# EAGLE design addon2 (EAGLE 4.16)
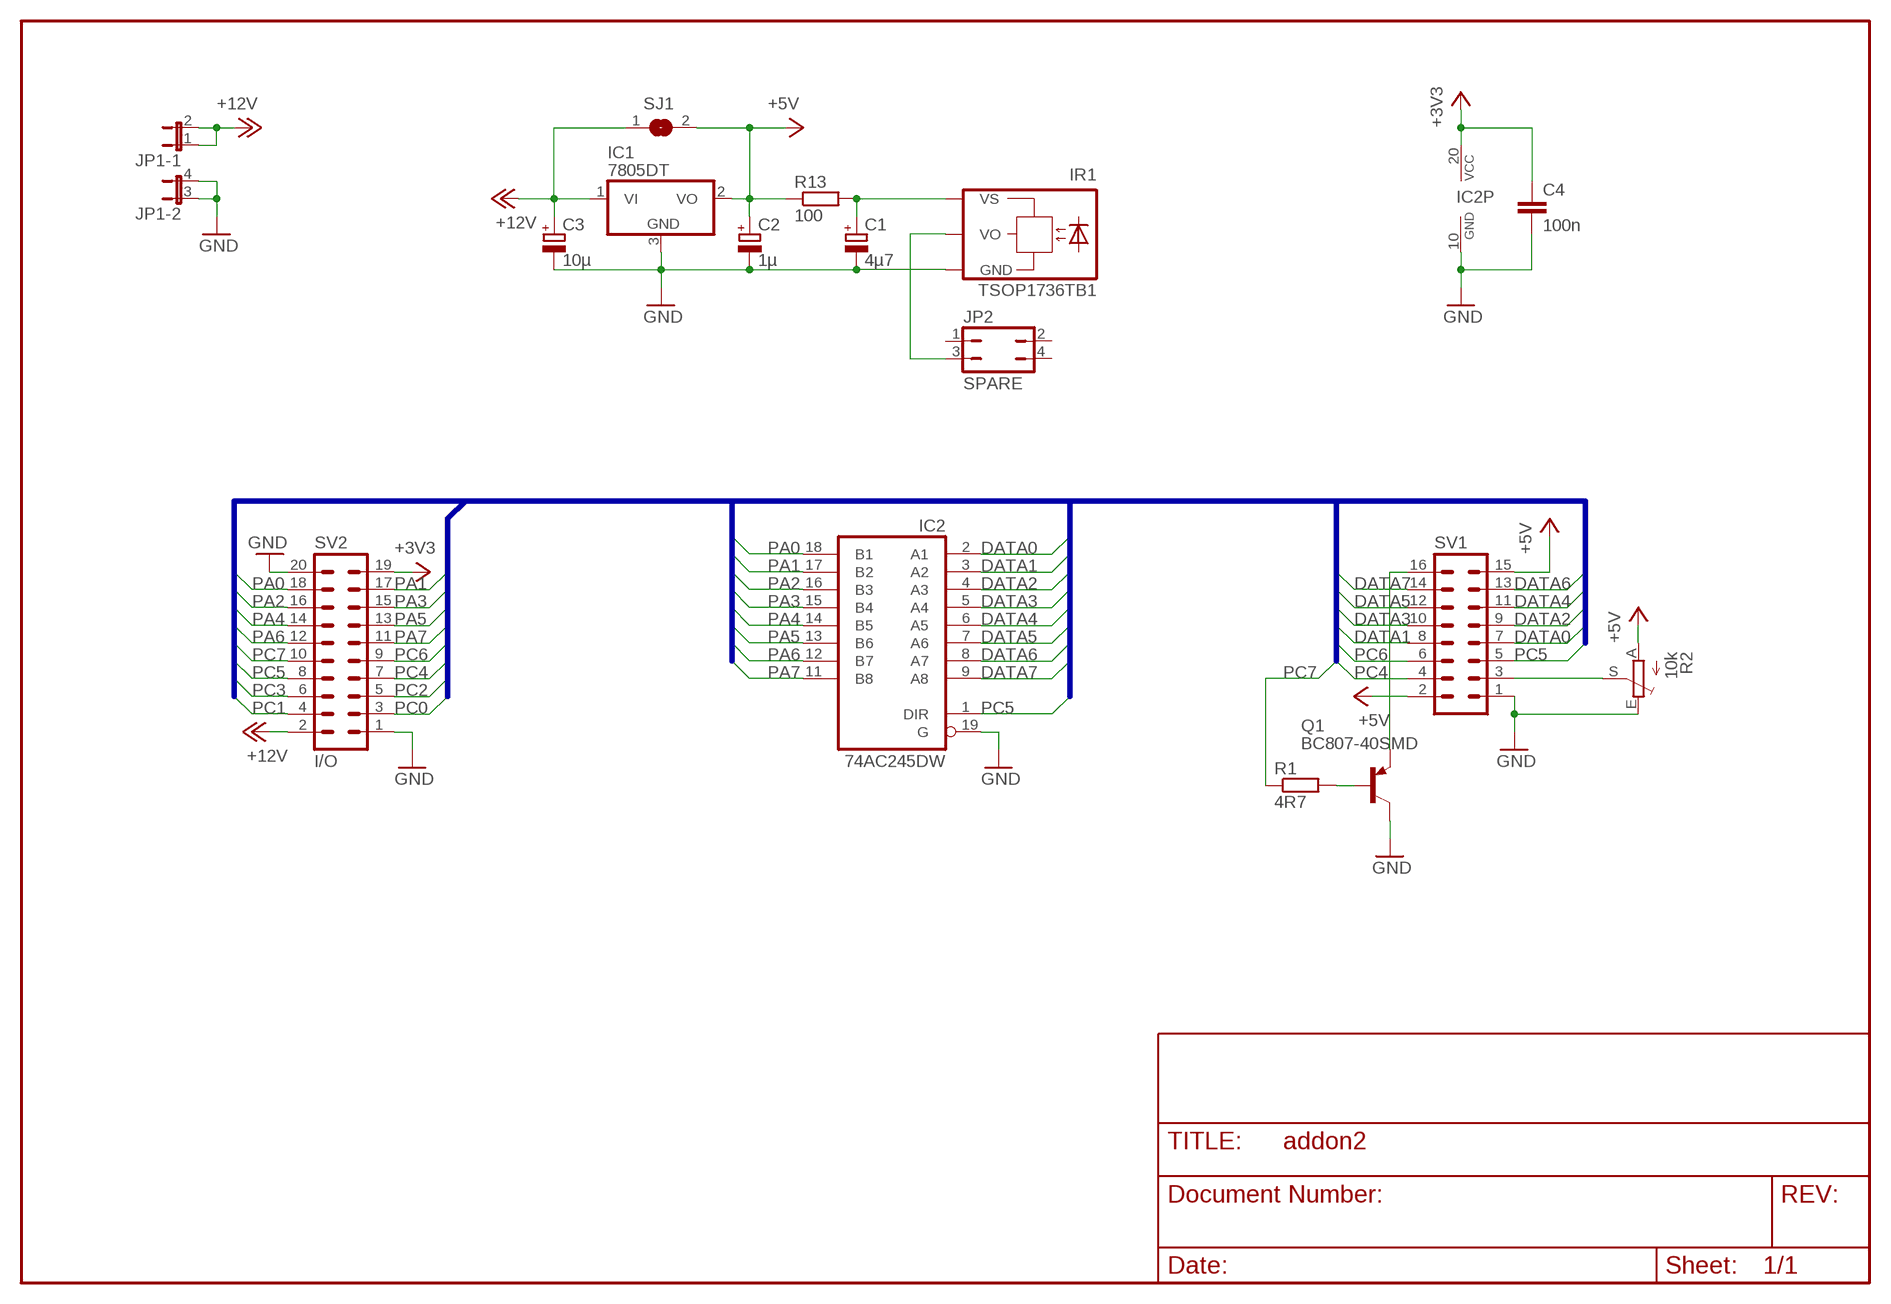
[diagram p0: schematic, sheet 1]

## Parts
C1  4µ7  CPOL-EUSMCA  [SMC_A]
C2  1µ  CPOL-EUSMCA  [SMC_A]
C3  10µ  CPOL-EUSMCD  [SMC_D]
C4  100n  C-EUC0805  [C0805]
IC1  7805DT  [TO252]
IC2  74AC245DW  [SO20W]
IR1  TSOP1736TB1  [TSOP17_TB1]
JP1  JP2QE  [JP2Q]
JP2  SPARE  JP2Q  [JP2Q]
Q1  BC807-40SMD  [SOT23-BEC]
R1  4R7  R-EU_R1206  [R1206]
R2  10k  TRIM_EU-LI10  [LI10]
R13  100  R-EU_R0805  [R0805]
SJ1  SJ  [SJ]
SV1  ML16L  [ML16L]
SV2  I/O  MA10-2  [MA10-2]

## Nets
+3V3: C4.1 IC2.20(VCC) SV2.19
+5V: C2.+ IC1.2(VO) R2.A R13.1 SJ1.2 SV1.2 SV1.15
+12V: C3.+ IC1.1(VI) JP1.1 JP1.2 SJ1.1 SV2.2
DATA0: IC2.2(A1) SV1.7
DATA1: IC2.3(A2) SV1.8
DATA2: IC2.4(A3) SV1.9
DATA3: IC2.5(A4) SV1.10
DATA4: IC2.6(A5) SV1.11
DATA5: IC2.7(A6) SV1.12
DATA6: IC2.8(A7) SV1.13
DATA7: IC2.9(A8) SV1.14
GND: C1.- C2.- C3.- C4.2 IC1.3(GND) IC2.10(GND) IC2.19(G) IR1.GND JP1.3 JP1.4 Q1.C R2.E SV1.1 SV2.1 SV2.20
N$1: R2.S SV1.3
N$2: Q1.B R1.2
N$3: Q1.E SV1.16
N$21: C1.+ IR1.VS R13.2
N$22: IR1.VO JP2.3
PA0: IC2.18(B1) SV2.18
PA1: IC2.17(B2) SV2.17
PA2: IC2.16(B3) SV2.16
PA3: IC2.15(B4) SV2.15
PA4: IC2.14(B5) SV2.14
PA5: IC2.13(B6) SV2.13
PA6: IC2.12(B7) SV2.12
PA7: IC2.11(B8) SV2.11
PC0: SV2.3
PC1: SV2.4
PC2: SV2.5
PC3: SV2.6
PC4: SV1.4 SV2.7
PC5: IC2.1(DIR) SV1.5 SV2.8
PC6: SV1.6 SV2.9
PC7: R1.1 SV2.10
Unconnected: JP2.1 JP2.2 JP2.4

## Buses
PA[0..7],PC[0..7],DATA[0..7]

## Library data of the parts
C1-C3 = rcl:CPOL-EU: POLARIZED CAPACITOR, European symbol
C4 = rcl:C-EU: CAPACITOR, European symbol
IC1 = linear:78*: Positive VOLTAGE REGULATOR Source: http://cache.national.com/ds/LM/LM78L05.pdf http://www.fairchildsemi.com/ds/LM/LM7805.pdf
IC2 = 74xx-eu:74*245: Octal BUS TRANSCEIVER, 3-state
IR1 = telefunken:TSOP17*TB1: TSOP17..TB1 IR Receiver Modules for Remote Control Systems Source: http://www.vishay.com/docs/82042/82042.pdf
JP1 = jumper:JP2QE: JUMPER
JP2 = jumper:JP2Q: JUMPER
Q1 = transistor-pnp:BC807*: PNP Transistror
R1 R13 = rcl:R-EU_: RESISTOR, European symbol
R2 = pot:TRIM_EU-: POTENTIOMETER
SJ1 = jumper:SJ: SMD solder JUMPER
SV1 = con-harting-ml:ML16: HARTING
SV2 = con-lstb:MA10-2: PIN HEADER

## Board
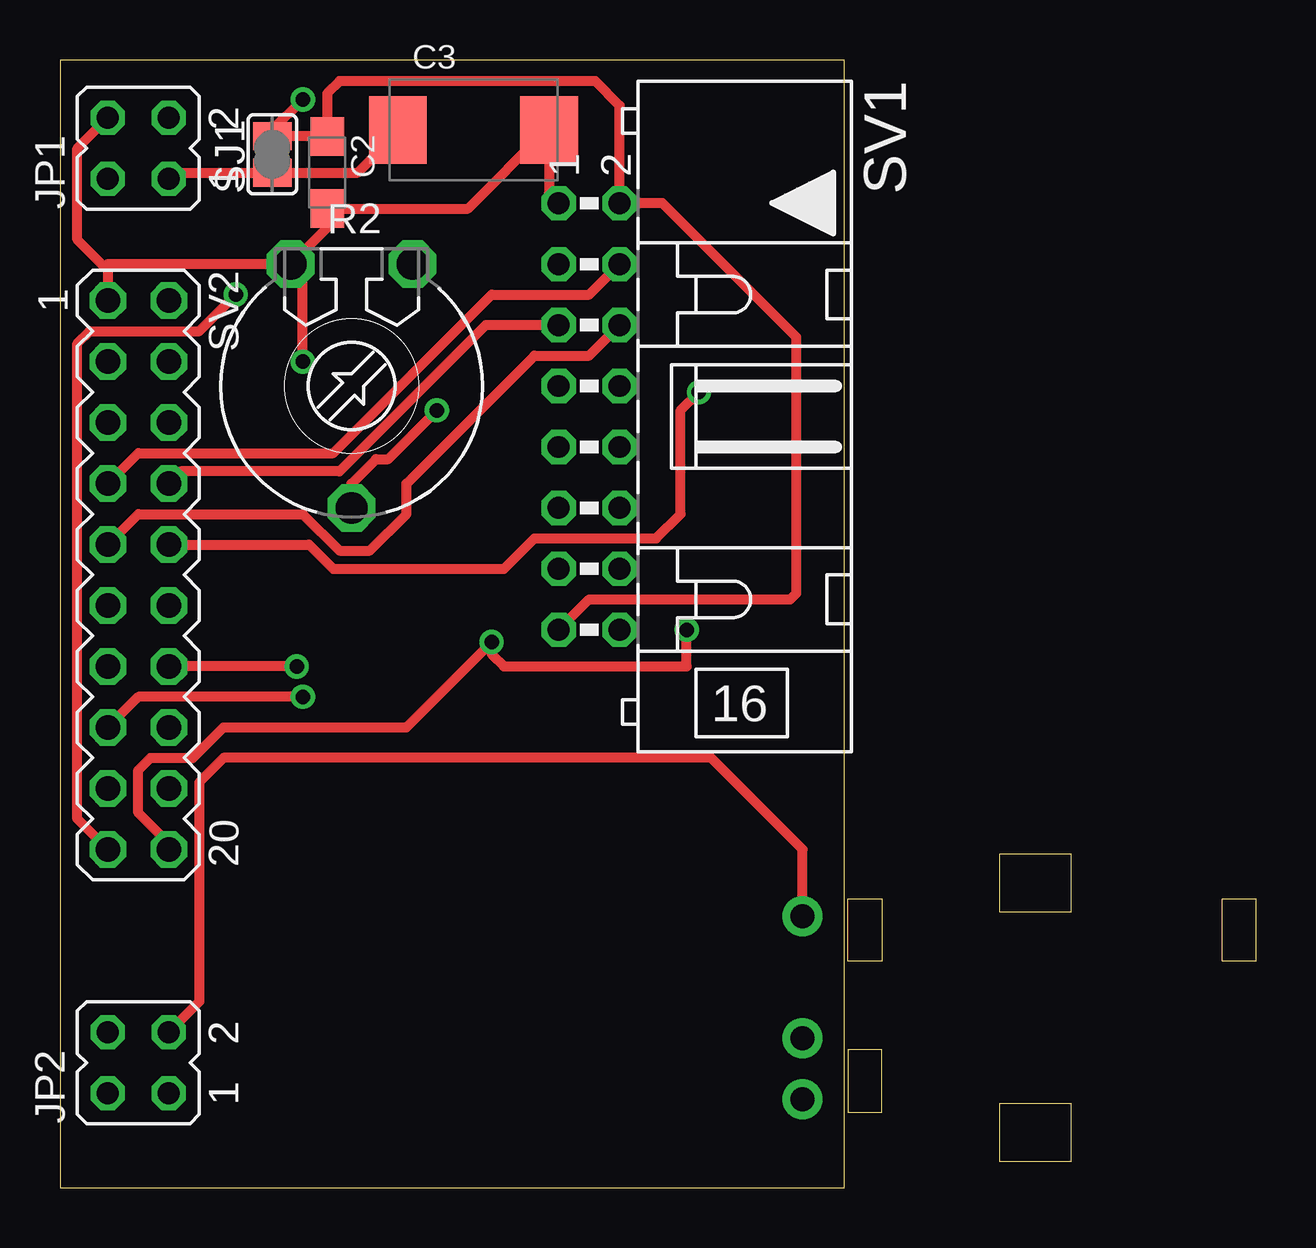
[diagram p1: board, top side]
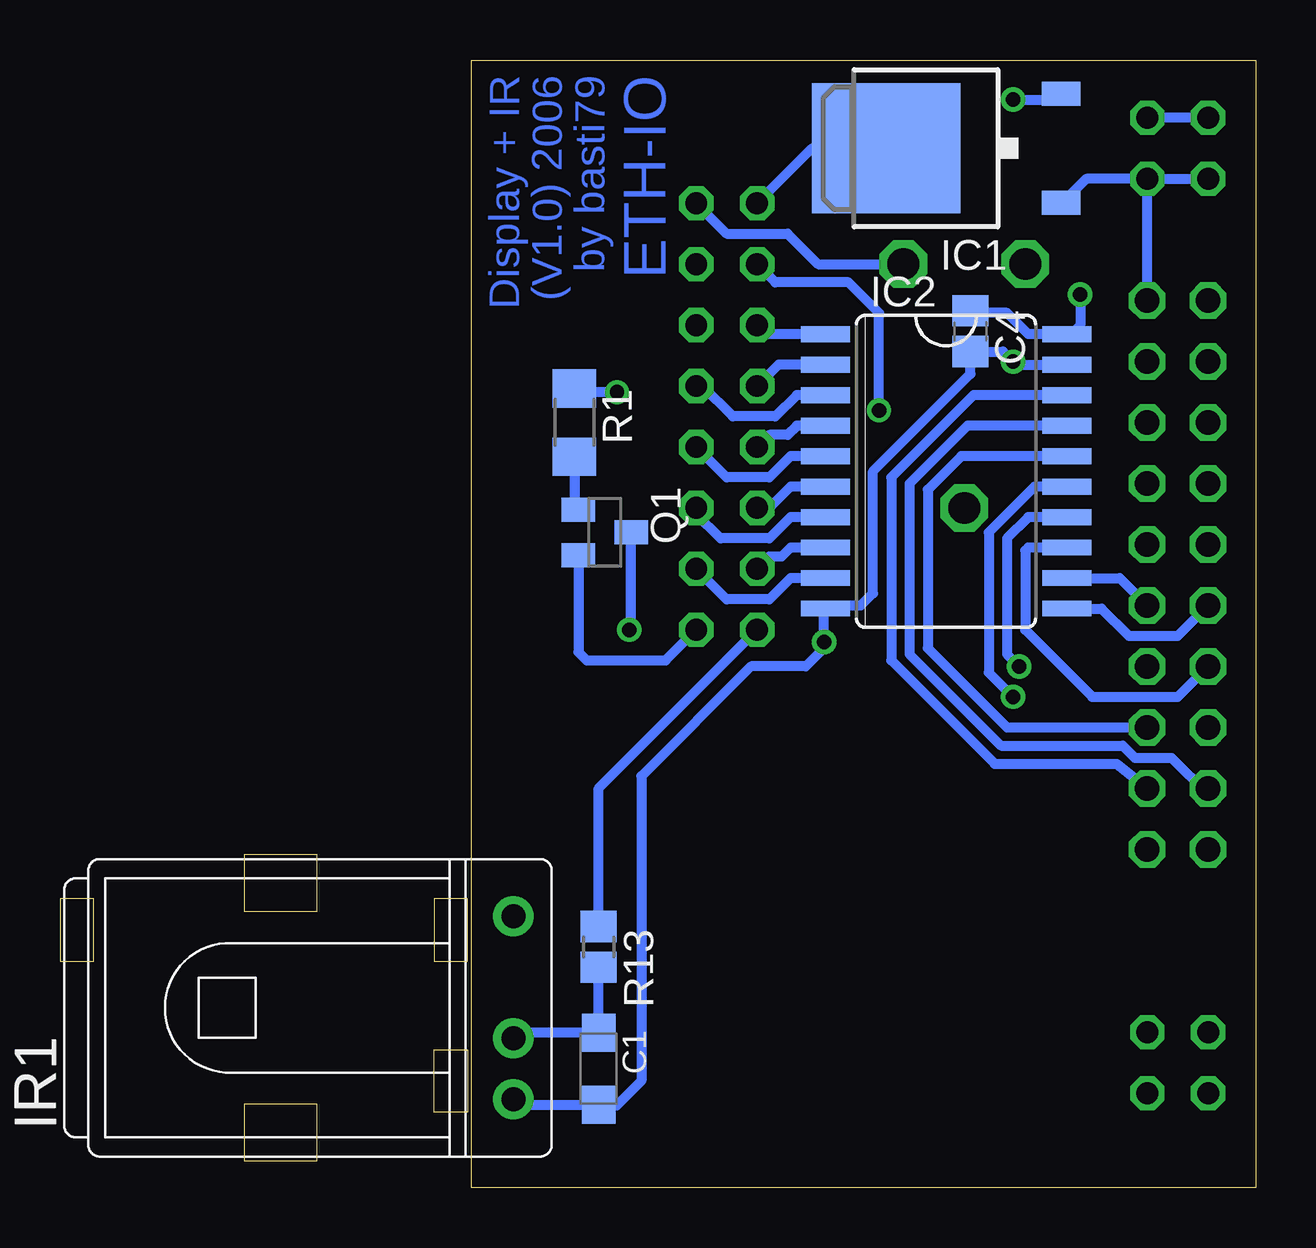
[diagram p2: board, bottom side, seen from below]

Size 49.85 x 46.98 mm. Coordinates in mm from the lower left corner, seen from the top.
Outline: 0,0 32.69,0 32.69,46.98 0,46.98 0,0
Copper layers (1*16): Top 0.035mm / dielectric 1.5mm / Bottom 0.035mm
Design rules "default": minimum track width 10mil, minimum drill 20mil, track to track 8mil, track to pad 8mil, pad to pad 8mil, via to via 8mil, smd to smd 8mil, copper to edge 20mil, drill to drill 8mil, minimum pad ring 10mil, minimum via ring 8mil, stop-mask expansion 4mil, vias tented up to drill 0mil, thermal gap 10mil
tKeepout: area 6.6,-0.1 to 23.3,16.9
bKeepout: area 6.6,-0.1 to 23.3,16.9; area 0,39.7 to 6.8,47.1; area 22.6,16.1 to 31.2,22.2

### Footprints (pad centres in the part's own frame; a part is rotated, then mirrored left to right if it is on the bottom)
SMC_A = smd 1.6 x 1.4: + -1.5,0; - 1.5,0
SMC_D = smd 2.4 x 2.8: + -3.15,0; - 3.15,0
C0805 = smd 1.3 x 1.5: 1 -0.85,0; 2 0.85,0
TO252 = smd 1 x 1.6: 1 -2.28,-4.8; 2 2.28,-4.8 | smd 5.4 x 6.2: 3 0,2.5
SO20W = smd 0.66 x 2.032: 1 -5.715,-5.029; 2 -4.445,-5.029; 3 -3.175,-5.029; 4 -1.905,-5.029; 5 -0.635,-5.029; 6 0.635,-5.029; 7 1.905,-5.029; 8 3.175,-5.029; 9 4.445,-5.029; 10 5.715,-5.029; 11 5.715,5.029; 12 4.445,5.029; 13 3.175,5.029; 14 1.905,5.029; 15 0.635,5.029; 16 -0.635,5.029; 17 -1.905,5.029; 18 -3.175,5.029; 19 -4.445,5.029; 20 -5.715,5.029
TSOP17_TB1 = drill 1 pad 1.676 round: GND 0,-3.81; VO 0,3.81; VS 0,-1.27
JP2Q = drill 0.914 octagon: 1 -1.27,-1.27; 2 -1.27,1.27; 3 1.27,-1.27; 4 1.27,1.27
SOT23-BEC = smd 1 x 1.4: B -0.95,-1.1; C 0,1.1; E 0.95,-1.1
R1206 = smd 1.6 x 1.803: 1 -1.422,0; 2 1.422,0
LI10 = drill 1.321 octagon: A -2.54,-5.08; E 2.54,-5.08; S 0,5.08
R0805 = smd 1.3 x 1.5: 1 -0.85,0; 2 0.85,0
SJ = smd 1.168 x 1.6: 1 -0.762,0; 2 0.762,0
ML16L = drill 0.914 octagon: 1 -8.89,-1.27; 2 -8.89,1.27; 3 -6.35,-1.27; 4 -6.35,1.27; 5 -3.81,-1.27; 6 -3.81,1.27; 7 -1.27,-1.27; 8 -1.27,1.27; 9 1.27,-1.27; 10 1.27,1.27; 11 3.81,-1.27; 12 3.81,1.27; 13 6.35,-1.27; 14 6.35,1.27; 15 8.89,-1.27; 16 8.89,1.27
MA10-2 = drill 1.016 octagon: 1 -11.43,-1.27; 2 -11.43,1.27; 3 -8.89,-1.27; 4 -8.89,1.27; 5 -6.35,-1.27; 6 -6.35,1.27; 7 -3.81,-1.27; 8 -3.81,1.27; 9 -1.27,-1.27; 10 -1.27,1.27; 11 1.27,-1.27; 12 1.27,1.27; 13 3.81,-1.27; 14 3.81,1.27; 15 6.35,-1.27; 16 6.35,1.27; 17 8.89,-1.27; 18 8.89,1.27; 19 11.43,-1.27; 20 11.43,1.27

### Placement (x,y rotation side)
C1  27.39,4.95 270 bottom
C2  11.14,42.29 270 top
C3  17.23,44.06 0 top
C4  11.9,35.68 270 bottom
IC1  12.92,43.3 90 bottom
IC2  12.92,29.84 270 bottom
IR1  30.95,7.49 0 bottom
JP1  3.26,43.3 90 top
JP2  3.26,5.2 90 top
Q1  27.14,27.3 270 bottom
R1  28.41,31.87 270 bottom
R2  12.15,33.4 180 top
R13  27.39,10.03 270 bottom
SJ1  8.85,43.05 90 top
SV1  22.06,32.13 270 top
SV2  3.26,25.52 270 top

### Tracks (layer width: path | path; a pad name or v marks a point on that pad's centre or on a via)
+3V3  (via drill 0.6)
  Top 0.406: SV2.19 0.72,15.36 0.72,35.17 1.23,35.68 5.8,35.68 v7.33,37.21
  Bottom 0.406: C4.1 11.9,36.44 10.38,36.44 9.49,35.55 IC2.20 7.89,35.48 7.84,35.43 7.33,35.94 v7.33,37.21
+5V  (via drill 0.6)
  Top 0.406: v10.12,45.33 8.85,44.06 SJ1.2 11.14,43.81 C2.+ 11.14,45.59 11.65,46.1 22.31,46.1 23.33,45.08 23.33,41.27 23.08,41.02 SV1.2 25.11,41.02 30.7,35.43 30.7,24.76 30.44,24.51 22.06,24.51 SV1.15
  Bottom 0.406: R2.A 18.25,38.48 19.52,39.75 22.06,39.75 SV1.2 | 8.1,45.58 8.09,45.59 | 8.1,45.58 IC1.2 | v10.12,45.33 8.34,45.33 8.1,45.58 | R13.1 27.39,16.63 SV1.15
+12V
  Top 0.406: C3.+ 14.19,44.06 12.41,42.29 SJ1.1 4.79,42.29 JP1.1
  Bottom 0.406: JP1.1 4.53,41.78 4.28,42.03 JP1.2 | 4.53,36.7 SV2.2 JP1.1 | IC1.1 8.1,41.02 8.09,41.02 7.07,42.03 JP1.1
DATA0
  Bottom 0.406: IC2.2 19.9,34.28 SV1.7
DATA1
  Bottom 0.406: IC2.3 19.14,33.02 20.03,32.13 21.81,32.13 23.08,33.4 SV1.8
DATA2
  Bottom 0.406: IC2.4 19.14,31.75 19.52,31.36 20.28,31.36 SV1.9
DATA3
  Bottom 0.406: IC2.5 19.39,30.48 20.28,29.59 22.06,29.59 SV1.10
DATA4
  Bottom 0.406: SV1.11 20.28,28.32 19.39,29.2 IC2.6
DATA5
  Bottom 0.406: IC2.7 19.39,27.93 20.28,27.05 22.31,27.05 23.33,28.06 SV1.12
DATA6
  Bottom 0.406: IC2.8 19.39,26.66 19.77,26.28 20.28,26.28 SV1.13
DATA7
  Bottom 0.406: IC2.9 19.39,25.39 20.28,24.51 22.06,24.51 SV1.14
GND  (via drill 0.6)
  Top 0.406: v10.12,34.41 10.12,37.97 R2.E | SV1.1 20.38,41.42 C3.- 20.28,44.06 17,40.79 C2.- 11.14,40 R2.E | v26.12,23.24 26.12,21.71 18.5,21.71 18,22.22 v18,22.73 14.44,19.17 6.82,19.17 5.55,17.9 3.77,17.9 3.26,17.39 3.26,15.62 4.53,14.35 SV2.20 | 1.99,38.22 1.99,38.48 R2.E | JP1.4 0.72,43.3 0.72,39.49 1.99,38.22 | 1.99,38.22 SV2.1
  Bottom 0.406: IC2.19 10,34.28 v10.12,34.41 10.54,34.83 C4.2 11.9,33.9 15.96,29.84 15.96,24.76 16.47,24.25 17.74,24.25 17.94,24.05 | 17.94,24.05 18,24 v18,22.73 18,22.47 18.76,21.71 21.04,21.71 25.62,17.14 25.62,4.44 26.63,3.42 30.44,3.42 30.7,3.68 IR1.GND 30.72,3.45 C1.- | 17.94,24.05 IC2.10 | JP1.4 JP1.3 | IC1.3 18.5,43.3 SV1.1 | Q1.C 26.04,23.32 v26.12,23.24
N$1  (via drill 0.6)
  Top 0.406: R2.S 12.15,29.33 13.17,30.35 13.68,30.35 v15.71,32.38
  Bottom 0.406: v15.71,32.38 15.71,36.44 16.98,37.71 20.03,37.71 SV1.3
N$2
  Bottom 0.406: Q1.B 28.34,28.25 28.41,28.32 R1.2
N$3
  Bottom 0.406: Q1.E 28.24,22.3 27.9,21.97 24.6,21.97 SV1.16
N$21
  Bottom 0.406: IR1.VS 30.7,6.22 30.47,6.45 C1.+ R13.2
N$22
  Top 0.406: IR1.VO 30.95,14.09 27.14,17.9 6.82,17.9 5.8,16.89 5.8,7.74 JP2.3
PA0
  Bottom 0.406: IC2.18 11.77,33.02 15.2,29.59 15.2,21.97 10.88,17.65 5.8,17.65 SV2.18
PA1
  Bottom 0.406: IC2.17 12.03,31.75 14.44,29.33 14.44,22.22 10.63,18.41 5.55,18.41 5.04,17.9 3.52,17.9 1.99,16.38 SV2.17
PA2
  Bottom 0.406: IC2.16 12.28,30.48 13.68,29.08 13.68,22.47 10.38,19.17 SV2.16
PA3  (via drill 0.6)
  Top 0.406: v10.12,20.44 3.26,20.44 SV2.15
  Bottom 0.406: IC2.15 9.23,29.2 11.14,27.3 11.14,21.46 v10.12,20.44
PA4  (via drill 0.6)
  Top 0.406: v9.87,21.71 SV2.14
  Bottom 0.406: IC2.14 9.49,27.93 10.38,27.05 10.38,22.22 v9.87,21.71
PA5
  Bottom 0.406: IC2.13 9.49,26.66 9.61,26.54 9.61,23.24 6.82,20.44 3.26,20.44 SV2.13
PA6
  Bottom 0.406: IC2.12 5.68,25.39 SV2.12
PA7
  Bottom 0.406: IC2.11 6.44,24.12 5.3,22.98 3.26,22.98 SV2.11
PC4
  Top 0.406: SV2.7 3.26,30.6 11.39,30.6 18,37.21 22.06,37.21 SV1.4
PC5
  Top 0.406: SV1.5 17.74,35.94 11.65,29.84 5.04,29.84 SV2.8
  Bottom 0.406: IC2.1 20.41,35.55 SV1.5
PC6
  Top 0.406: SV2.9 3.26,28.06 10.12,28.06 11.65,26.54 12.92,26.54 14.44,28.06 14.44,29.33 19.77,34.67 22.06,34.67 SV1.6
PC7  (via drill 0.6)
  Top 0.406: SV2.10 10.38,26.79 11.39,25.78 18.5,25.78 19.77,27.05 24.85,27.05 25.87,28.06 25.87,32.38 v26.63,33.14
  Bottom 0.406: R1.1 28.41,33.14 v26.63,33.14

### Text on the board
Bottom: ETH-IO | by basti79 | (V1.0) 2006 | Display + IR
